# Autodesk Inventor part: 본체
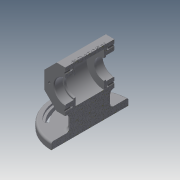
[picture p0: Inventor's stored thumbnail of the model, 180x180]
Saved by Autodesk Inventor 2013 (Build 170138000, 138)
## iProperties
Created: 2017-06
Part Number: 본체
Material: 일반
Document SubType Name: Modeling
Designer: Administrator
Density: 1 g/cm^3
Author: Administrator
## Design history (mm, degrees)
sketch "스케치1"
  geometry: L1 (30, -12.426)-(12.426, -30); L2 (12.426, -30)-(-12.426, -30); L3 (-12.426, -30)-(-30, -12.426); L4 (-30, -12.426)-(-30, 12.426); L5 (-30, 12.426)-(-12.426, 30); L6 (-12.426, 30)-(12.426, 30); L7 (12.426, 30)-(30, 12.426); L8 (30, 12.426)-(30, -12.426); 2 further points
  constraints: 16 end point, 1 coincident, 17 other
  dimensions: "d0" = 30 distance from line of point (0, 0) L8
extrude "돌출1" new body sketch "스케치1" stored distance "d1" = 70; taper "d2" = 0 deg
sketch "스케치2"
  geometry: L1 (-35, -30)-(-35, 30) reference; L2 (-35, 30)-(35, 30) reference; L3 (35, 30)-(35, -30) reference; L4 (35, -30)-(-35, -30) reference; L5 (-35, 0)-(35, 0); L6 (-35, 16)-(-23, 16); L7 (-23, 16)-(-23, 14); L8 (-23, 14)-(-20, 14); L9 (-20, 14)-(-20, 25); L10 (-20, 25)-(20, 25); L11 (20, 25)-(20, 14); L12 (20, 14)-(23, 14); L13 (23, 14)-(23, 16); L14 (23, 16)-(35, 16); L15 (-35, 16)-(-35, 0); L16 (35, 16)-(35, 0); 1 further point
  constraints: 24 end point, 7 parallel, 4 perpendicular, 2 midpoint, 2 point on line
  dimensions: "d3" = 32 diameter of L6 L5; "d5" = 28 diameter of L8 L5; "d6" = 50 diameter of L10 L5; "d7" = 28 diameter of L12 L5; "d8" = 32 diameter of L14 L5; "d9" = 40 distance of L9.end L10.end; "d10" = 12 distance of L6.start L6.end; "d11" = 12 distance of L13.end L14.end; "d12" = 3 distance of L7.end L8.end
revolve "회전1" sketch "스케치2" stored, may be unused: angle "d13" = 90 deg
node "작업 평면1"
sketch "스케치3"
  geometry: C1 r 55 at (0, 0); 1 further point
  constraints: 1 centre point, 1 coincident
  dimensions: "d15" = 110 diameter of C1
extrude "돌출2" join sketch "스케치3" distance "d16" = 10; taper "d17" = 0 deg
sketch "스케치4"
  geometry: L1 (0, 0)-(0, 55); L2 (0, 0)-(0, -55); L3 (0, 0)-(-38.891, 38.891); L4 (0, 0)-(38.891, -38.891); L5 (0, 0)-(-38.891, -38.891); L6 (0, 0)-(38.891, 38.891); L7 (0, 0)-(-55, 0); L8 (0, 0)-(55, 0); A1 r 43 centre (0, 0) between (-30.406, 30.406) and (30.406, 30.406); A2 r 5 centre (-30.406, 30.406) between (-33.941, 33.941) and (-26.87, 26.87); A3 r 5 centre (30.406, -30.406) between (33.941, -33.941) and (26.87, -26.87); A4 r 5 centre (-30.406, -30.406) between (-26.87, -26.87) and (-33.941, -33.941); A5 r 38 centre (0, 0) between (-26.87, -26.87) and (26.87, -26.87); A6 r 38 centre (0, 0) between (26.87, 26.87) and (-26.87, 26.87); A7 r 48 centre (0, 0) between (-33.941, -33.941) and (33.941, -33.941); A8 r 48 centre (0, 0) between (33.941, 33.941) and (-33.941, 33.941); A9 r 2 centre (-30.406, 30.406) between (-31.82, 31.82) and (-28.991, 28.991); A10 r 2 centre (30.406, 30.406) between (28.991, 28.991) and (31.82, 31.82); A11 r 2 centre (30.406, -30.406) between (31.82, -31.82) and (28.991, -28.991); A12 r 2 centre (-30.406, -30.406) between (-28.991, -28.991) and (-31.82, -31.82); A13 r 45 centre (0, 0) between (31.82, 31.82) and (-31.82, 31.82); A14 r 41 centre (0, 0) between (28.991, 28.991) and (-28.991, 28.991); A15 r 41 centre (0, 0) between (-28.991, -28.991) and (28.991, -28.991); A16 r 45 centre (0, 0) between (-31.82, -31.82) and (31.82, -31.82); A17 r 5 centre (30.406, 30.406) between (26.87, 26.87) and (33.941, 33.941); 1 further point
  constraints: 36 point on circle, 17 centre point, 16 end point, 11 coincident, 9 point on line, 4 tangent, 2 collinear, 1 perpendicular, 1 vertical, 9 other
  dimensions: "d19" = 86 diameter of A1; "d21" = 45 deg angle of L3 L7; "d22" = 45 deg angle of L8 L6; "d23" = 45 deg angle of L5 L7; "d24" = 45 deg angle of L8 L4; "d25" = 10 diameter of A2; "d27" = 10 diameter of A3; "d28" = 10 diameter of A4; "d29" = 4 diameter of A9; "d30" = 4 diameter of A10; "d31" = 4 diameter of A11; "d32" = 4 diameter of A12
extrude "돌출3" cut sketch "스케치4" distance "d33" = 3; taper "d34" = 0 deg
extrude "돌출4" cut sketch "스케치4" stored distance "d35" = 3; taper "d36" = 0 deg
sketch "스케치5"
  geometry: L1 (-24, -5)-(24, -5); L2 (24, -5)-(24, 5); L3 (24, 5)-(-24, 5); L4 (-24, 5)-(-24, -5); L5 (-24, -5)-(24, 5); L6 (24, -5)-(-24, 5); C1 r 55 at (0, 0) reference; C2 r 5 at (24, 0); C3 r 5 at (-24, 0)
  constraints: 12 end point, 4 midpoint, 2 centre point, 2 parallel, 1 horizontal, 1 perpendicular
  dimensions: "d37" = 48 distance of L3.end L2.end; "d38" = 10 distance of L2.end L1.end; "d40" = 10 diameter of C2; "d41" = 10 diameter of C3
extrude "돌출5" join sketch "스케치5" stored distance "d42" = 3; taper "d43" = 0 deg
sketch "스케치6" dims "d44" = 46
  geometry: C1 r 16 at (0, 0) reference; 2 further points
  constraints: 2 horizontal alignment, 1 coincident, 2 other
hole "구멍1" sketch "스케치6" at (23, 0) diameter "d45" = 3.242; stored, may be unused: countersink angle "d49" = 90 deg, drill point angle "d51" = 118 deg; dims "d46" = 8, "d47" = 4, "d48" = 2, "d50" = 10
sketch "스케치7"
  geometry: C1 r 8 at (35, 12.426); 1 further point
  constraints: 1 centre point, 1 coincident
  dimensions: "d55" = 16 diameter of C1
extrude "돌출6" join sketch "스케치7" distance "d56" = 7; taper "d57" = 0 deg
sketch "스케치8"
  geometry: C1 r 8 at (0, 0) reference
hole "구멍2" sketch "스케치8" at (0, 0) diameter "d58" = 8; stored, may be unused: countersink angle "d62" = 90 deg, drill point angle "d64" = 0 deg; dims "d59" = 8, "d60" = 4, "d61" = 2, "d63" = 10
sketch "스케치9"
  geometry: L1 (0, 0)-(0, 24.853) reference; L2 (70, 42.426)-(0, 42.426) reference; 2 further points
  constraints: 1 other
  dimensions: "d66" = 30 distance from line of L2 point (35, 12.426); "d67" = 35 distance from line of L1 point (35, 12.426)
feature "엠보싱1" sketch "스케치9" dims "d0" = 30, "d3" = 32, "d5" = 28, "d6" = 50, "d7" = 28, "d8" = 32, "d9" = 40, "d10" = 12, "d11" = 12, "d12" = 3, "d68" = 0.5, "d69" = 0
fillet "모깎기1" dims "d70" = 3
fillet "모깎기2" dims "d71" = 5
fillet "모깎기3" dims "d72" = 1
fillet "모깎기4" dims "d73" = 3
chamfer "모따기1" distance "d74" = 1; stored, may be unused: second distance "d75" = 2, angle "d76" = 45 deg
node "솔리드1"
pattern_circular "원형 패턴1" dims angle "d53" = 360 deg
mirror "대칭1"
node "절단 모서리 투영1"
other parameters: "d14" = -62, "d18" = 96, "d20" = 76
